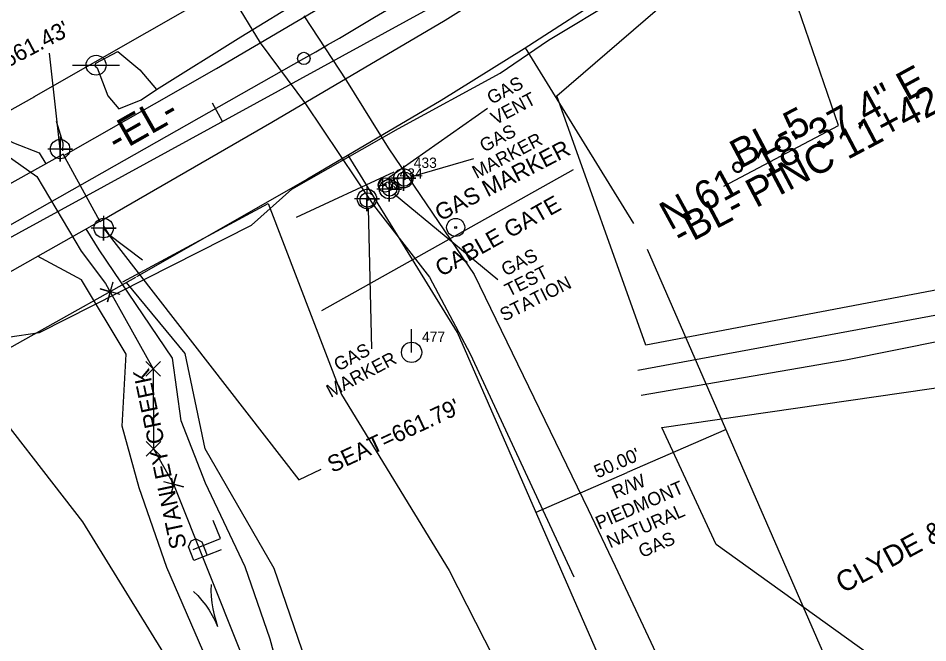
# Model space of a CAD drawing. Extents: x 1380524 to 1382335, y 594765 to 596944.
# Drawn here: x 1381675.7 to 1381895.1, y 595421 to 595571.8 of the extents above; entities that cross this region are included whole.
import ezdxf

# ---------------------------------------------------------------- set-up
doc = ezdxf.new("R2010")
doc.units = 0
for name, color, linetype in [('DTM Contours Minor Text', 7, 'Continuous'), ('Exist DTM Regular Point CELL', 7, 'Continuous'), ('Exist Horizontal Alignment', 7, 'Continuous'), ('Exist Horizontal Alignment Direction Label', 7, 'Continuous'), ('Exist Horizontal Alignment Station Label', 7, 'Continuous'), ('Exist Horizontal Baseline Alignment', 7, 'Continuous'), ('Exist Horizontal Baseline Alignment Direction Label', 7, 'Continuous'), ('Exist Horizontal Baseline Alignment Station Label', 7, 'Continuous'), ('Exist Horizontal Baseline Alignment Tick small', 7, 'Continuous'), ('Exist Hydro Jurisdictional Stream or Body of Water', 7, 'Continuous'), ('Exist Hydro Jurisdictional Stream or Body of Water Text', 7, 'Continuous'), ('Exist Other Culture Fence Line', 7, 'Continuous'), ('Exist Right of Way Line', 7, 'Continuous'), ('Exist Roads Concrete Median Barrier Cogo Comment', 7, 'Continuous'), ('Exist Roads EOP', 7, 'Continuous'), ('Exist Structure Major Bridge Seat Cogo Point CELL', 7, 'Continuous'), ('Exist Structure Major Bridge Seat Top Elevation', 7, 'Continuous'), ('Exist Structure Major Bridge WW', 7, 'Continuous'), ('Exist Utilities Gas UG Line', 7, 'Continuous'), ('Exist Utilities Gas UG Line Cogo Number', 7, 'Continuous'), ('Exist Utilities Gas UG Line Cogo Point CELL', 7, 'Continuous'), ('Exist Utilities Gas UG Line SUE', 7, 'Continuous'), ('Exist Utilities Other Located Object Leader', 7, 'Continuous'), ('Exist Utilities Power Tower CELL', 7, 'Continuous'), ('Exist Utilities Power Tower Text', 7, 'Continuous'), ('Exist Utilities Telephone UG Cable', 7, 'Continuous'), ('Exist Vegetation Tree CELL', 7, 'Continuous'), ('Prop Approach Slab Hatching', 7, 'Continuous'), ('Prop Drainage Ditch Boundaries', 7, 'Continuous'), ('Prop Drainage Structure Pipe Elbow CELL', 7, 'Continuous'), ('Prop Earthen Structure Cut Ditch Special Detail CELL', 7, 'Continuous'), ('Prop Earthen Structure Cut Ditch Special Detail Label', 7, 'Continuous'), ('Prop Earthen Structure Ditch Flow Line', 7, 'Continuous'), ('Prop Earthen Structure V Ditch Lateral Detail Label', 7, 'Continuous'), ('Prop Erosion Rip Rap Pad at Outlet CELL', 7, 'Continuous'), ('Prop Horizontal Alignment Tick Small', 7, 'Continuous'), ('Prop Plan Preparation Design Box Number Symbol CELL', 7, 'Continuous'), ('Scratch_Level_5', 7, 'Continuous'), ('Scratch_Level_6', 7, 'Continuous')]:
    doc.layers.add(name, color=color, linetype=linetype)

# ---------------------------------------------------------------- blocks, each defined once
blk = doc.blocks.new('EXIST UTILITIES OTHER LOCATED OBJECT')
at = {"layer": 'Prop Earthen Structure Cut Ditch Special Detail CELL'}
for radius in [0.0436, 0.0048]:
    blk.add_circle((0, 0), radius, dxfattribs=at)
blk = doc.blocks.new('EXIST HYDRO STREAM FLOW ARROW')
at = {"layer": 'DTM Contours Minor Text'}
blk.add_line((0, 0), (0, 0), dxfattribs=at)
for points in [[(-0.1, 0.04575), (-0.07325, 0.03375), (-0.04475, 0.0245), (-0.0165, 0.01575), (0.01175, 0.0095), (0.041, 0.00475), (0.07075, 0.0015), (0.1, 0)], [(-0.1, -0.04575), (-0.07325, -0.03375), (-0.04475, -0.0245), (-0.0165, -0.01575), (0.01175, -0.0095), (0.041, -0.00475), (0.07075, -0.0015), (0.1, 0)]]:
    blk.add_lwpolyline(points, dxfattribs=at)
blk = doc.blocks.new('EXIST UTILITIES POWER POLE')
at = {"layer": 'Exist Other Culture Fence Line'}
for q in [(0, 0.1125), (0, 0)]:
    blk.add_line((0, 0), q, dxfattribs=at)
blk.add_circle((0, 0), 0.049, dxfattribs=at)
blk = doc.blocks.new('EXIST UTILITIES TELEPHONE POLE')
at = {"layer": 'Exist Horizontal Alignment Station Label'}
for p, q in [((-0.1135, 0), (0.11325, 0)), ((0, 0), (0, 0))]:
    blk.add_line(p, q, dxfattribs=at)
blk.add_circle((0, 0), 0.04813, dxfattribs=at)
blk = doc.blocks.new('EXIST DTM REGULAR POINT')
at = {"layer": 'Exist DTM Regular Point CELL'}
blk.add_lwpolyline([(0, 0.06), (0, -0.06), (0, 0), (0.06, 0), (-0.06, 0)], dxfattribs=at)
blk.add_circle((0, 0), 0.0469, dxfattribs=at)

msp = doc.modelspace()

# ---------------------------------------------------------------- linework, layer by layer
at = {"layer": 'Exist Horizontal Alignment'}
msp.add_line((1381626.55, 595495.13), (1381744.58, 595562.07), dxfattribs=at)
msp.add_line((1381626.55, 595495.13), (1381744.58, 595562.07), dxfattribs=at)
msp.add_line((1381626.55, 595495.13), (1381744.58, 595562.07), dxfattribs=at)
msp.add_line((1381626.55, 595495.13), (1381744.58, 595562.07), dxfattribs=at)
msp.add_line((1381626.55, 595495.13), (1381744.58, 595562.07), dxfattribs=at)
msp.add_arc((1381362.24, 596236.19), 775, 299.56117, 307.3503, dxfattribs=at)
msp.add_arc((1381362.24, 596236.19), 775, 299.56117, 307.3503, dxfattribs=at)
msp.add_arc((1381362.24, 596236.19), 775, 299.56117, 307.3503, dxfattribs=at)
at = {"layer": 'Exist Horizontal Alignment Station Label'}
msp.add_circle((1381744.58, 595562.07), 1.5, dxfattribs=at)
at = {"layer": 'Exist Horizontal Baseline Alignment'}
msp.add_line((1381525.59, 595437.8), (1381849.7, 595615.17), dxfattribs=at)
at = {"layer": 'Exist Horizontal Baseline Alignment Station Label'}
for p, q in [((1381873.53, 595545.87), (1381849.7, 595615.17)), ((1381845.84, 595531.27), (1381873.53, 595545.87))]:
    msp.add_line(p, q, dxfattribs=at)
at = {"layer": 'Exist Horizontal Baseline Alignment Tick small'}
msp.add_line((1381724.92, 595546.88), (1381722.52, 595551.27), dxfattribs=at)
at = {"layer": 'Exist Hydro Jurisdictional Stream or Body of Water'}
for p, q in [((1381721.19, 595443.66), (1381721.19, 595443.66)), ((1381738.37, 595414.72), (1381736.48, 595421.87))]:
    msp.add_line(p, q, dxfattribs=at)
for points in [[(1381646.87, 595556.21), (1381674.51, 595541.69), (1381680.7, 595539.3), (1381682.35, 595536.63)], [(1381736.48, 595421.87), (1381730.41, 595439.34), (1381720.83, 595459.54), (1381715.01, 595474.58), (1381712.85, 595489.73), (1381695.18, 595515.91), (1381692.08, 595520.92)], [(1381721.27, 595416.77), (1381711.49, 595439.2), (1381704.86, 595458.45), (1381700.71, 595473.32), (1381701.7, 595490.68), (1381690.96, 595508.6), (1381680.33, 595514.31)], [(1381717.91, 595443.57), (1381724.48, 595446.19), (1381722.73, 595450.58)], [(1381724.59, 595443.45), (1381718.07, 595440.85), (1381716.75, 595444.16), (1381717.41, 595445.67), (1381718.49, 595446.1), (1381719.94, 595445.43), (1381721.26, 595442.12)]]:
    msp.add_lwpolyline(points, dxfattribs=at)
at = {"layer": 'Exist Other Culture Fence Line'}
for q in [(1381770.57, 595496.75), (1381770.57, 595491.13)]:
    msp.add_line((1381770.57, 595491.13), q, dxfattribs=at)
msp.add_circle((1381770.57, 595491.13), 2.45, dxfattribs=at)
at = {"layer": 'Exist Roads Concrete Median Barrier Cogo Comment'}
msp.add_line((1381742.83, 595523.74), (1381766.37, 595534.71), dxfattribs=at)
at = {"layer": 'Exist Roads EOP'}
for p, q in [((1381824.17, 595522.24), (1381798, 595564.6)), ((1381781.63, 595495.96), (1381755.23, 595538.7)), ((1381919.44, 595305.02), (1381827.47, 595515.95)), ((1381873.61, 595285.03), (1381781.63, 595495.96))]:
    msp.add_line(p, q, dxfattribs=at)
for points in [[(1381895.92, 595822.17), (1381902.47, 595793.76), (1381906.2, 595769.7), (1381907.97, 595742.61), (1381907.23, 595714.6), (1381902.73, 595686.65), (1381893.97, 595660.65), (1381884.45, 595642.32), (1381871.1, 595622.85), (1381855.36, 595606.07), (1381838.64, 595592.06), (1381819.68, 595578.62), (1381797.68, 595564.39), (1381777.69, 595551.91), (1381745.42, 595532.92), (1381704.18, 595509.33)], [(1381847.19, 595810.94), (1381853.34, 595784.3), (1381856.45, 595764.22), (1381857.93, 595741.64), (1381857.34, 595719.26), (1381854.03, 595698.69), (1381847.82, 595680.28), (1381841.48, 595668.07), (1381832.02, 595654.27), (1381820.95, 595642.47), (1381808.08, 595631.69), (1381791.64, 595620.03), (1381770.85, 595606.59), (1381751.76, 595594.66), (1381720.33, 595576.17), (1381679.35, 595552.72)], [(1381679.58, 595552.82), (1381632.97, 595526.73)], [(1381704, 595509.19), (1381657.4, 595483.1)]]:
    msp.add_lwpolyline(points, dxfattribs=at)
at = {"layer": 'Exist Structure Major Bridge Seat Top Elevation'}
msp.add_line((1381685.78, 595540.19), (1381683.22, 595563.35), dxfattribs=at)
at = {"layer": 'Exist Structure Major Bridge WW'}
for p, q in [((1381697.86, 595505.75), (1381697.86, 595505.75)), ((1381708.21, 595487.15), (1381708.21, 595487.15)), ((1381708.31, 595467.85), (1381708.31, 595467.85)), ((1381713.16, 595459.32), (1381713.16, 595459.32))]:
    msp.add_line(p, q, dxfattribs=at)
for points in [[(1381700.27, 595505.06), (1381695.46, 595506.43), (1381697.86, 595505.75), (1381697.18, 595503.34), (1381698.55, 595508.15)], [(1381709.98, 595485.4), (1381706.43, 595488.91), (1381708.21, 595487.15), (1381706.45, 595485.38), (1381709.97, 595488.93)], [(1381706.53, 595469.61), (1381710.08, 595466.1), (1381708.31, 595467.85), (1381710.07, 595469.63), (1381706.55, 595466.08)], [(1381710.75, 595459.98), (1381715.57, 595458.65), (1381713.16, 595459.32), (1381713.82, 595461.73), (1381712.5, 595456.91)]]:
    msp.add_lwpolyline(points, dxfattribs=at)
at = {"layer": 'Exist Utilities Gas UG Line'}
msp.add_lwpolyline([(1381819.69, 595439.52), (1382072.96, 594899.37)], dxfattribs=at)
at = {"layer": 'Exist Utilities Gas UG Line Cogo Point CELL'}
for points in [[(1381768.57, 595536.14), (1381768.57, 595530.14), (1381768.57, 595533.14), (1381771.57, 595533.14), (1381765.57, 595533.14)], [(1381765.15, 595533.53), (1381765.15, 595527.53), (1381765.15, 595530.53), (1381768.15, 595530.53), (1381762.15, 595530.53)], [(1381759.79, 595531.18), (1381759.79, 595525.18), (1381759.79, 595528.18), (1381762.79, 595528.18), (1381756.79, 595528.18)]]:
    msp.add_lwpolyline(points, dxfattribs=at)
for centre in [(1381768.57, 595533.14), (1381765.15, 595530.53), (1381759.79, 595528.18)]:
    msp.add_circle(centre, 2.34, dxfattribs=at)
at = {"layer": 'Exist Utilities Gas UG Line SUE'}
for p, q in [((1381723.79, 595582.73), (1381734.02, 595565.83)), ((1381744.6, 595572.32), (1381754.84, 595556.7)), ((1381734.02, 595565.83), (1381744.96, 595551.13)), ((1381754.84, 595556.7), (1381764.9, 595540.5)), ((1381744.96, 595551.13), (1381761.36, 595526.66)), ((1381764.9, 595540.5), (1381771.16, 595531.2)), ((1381771.16, 595531.2), (1381785.62, 595509.93)), ((1381761.36, 595526.66), (1381774.88, 595509.3)), ((1381774.88, 595509.3), (1381784.71, 595490.75)), ((1381785.62, 595509.93), (1381813.12, 595453.18)), ((1381784.71, 595490.75), (1381809.66, 595436.98)), ((1381813.12, 595453.18), (1381819.69, 595439.52))]:
    msp.add_line(p, q, dxfattribs=at)
at = {"layer": 'Exist Utilities Other Located Object Leader'}
for points in [[(1381765.09, 595533.32), (1381788.88, 595550.05)], [(1381770.61, 595533.58), (1381785.57, 595537.94)], [(1381766.46, 595529.33), (1381791.39, 595508.69)], [(1381760.08, 595525.97), (1381760.91, 595491.95)]]:
    msp.add_lwpolyline(points, dxfattribs=at)
at = {"layer": 'Exist Utilities Power Tower CELL'}
for p in [(1381846.4, 595472.53), (1381800.57, 595452.54)]:
    msp.add_line(p, (1381822.59, 595462.15), dxfattribs=at)
at = {"layer": 'Exist Utilities Power Tower Text'}
for p, q in [((1381697.86, 595505.75), (1381708.21, 595487.15)), ((1381708.21, 595487.15), (1381708.31, 595467.85)), ((1381708.31, 595467.85), (1381713.16, 595459.32)), ((1381713.16, 595459.32), (1381729.39, 595418.62))]:
    msp.add_line(p, q, dxfattribs=at)
at = {"layer": 'Exist Utilities Telephone UG Cable'}
for p, q in [((1381803.59, 595566.49), (1381829.59, 595582.19)), ((1381729.38, 595567.32), (1381749.29, 595579.5)), ((1381709.07, 595554.61), (1381729.38, 595567.32)), ((1381791.91, 595558.49), (1381803.59, 595566.49)), ((1381694.38, 595560.93), (1381699.7, 595563.71)), ((1381699.7, 595563.71), (1381705, 595559.32)), ((1381694.23, 595560.24), (1381694.38, 595560.93)), ((1381694.22, 595560.22), (1381694.74, 595559.79)), ((1381694.74, 595559.79), (1381697.26, 595553.01)), ((1381705, 595559.32), (1381709.07, 595554.61)), ((1381767.37, 595545.18), (1381791.91, 595558.49)), ((1381705.35, 595552.09), (1381709.07, 595554.61)), ((1381697.26, 595553.01), (1381699.93, 595549.91)), ((1381699.93, 595549.91), (1381705.35, 595552.09)), ((1381741.69, 595530.52), (1381767.37, 595545.18)), ((1381731.94, 595521.84), (1381741.69, 595530.52)), ((1381680.78, 595495.88), (1381731.94, 595521.84)), ((1381673.21, 595494.83), (1381680.78, 595495.88))]:
    msp.add_line(p, q, dxfattribs=at)
at = {"layer": 'Prop Drainage Ditch Boundaries'}
for points in [[(1381686.52, 595538.96), (1381642.72, 595514.47), (1381651.83, 595498.26)], [(1381651.83, 595498.26), (1381695.38, 595522.78), (1381686.52, 595538.96)]]:
    msp.add_lwpolyline(points, dxfattribs=at)
at = {"layer": 'Prop Drainage Structure Pipe Elbow CELL'}
for points in [[(1381991.91, 595521.81), (1381989.38, 595510.26), (1381981.68, 595508.51), (1381947.69, 595507.62), (1381920.27, 595504.37), (1381825.14, 595486.78)], [(1381825.94, 595480.83), (1381875.26, 595489.35), (1381922.43, 595498.8), (1381960.89, 595500.83), (1381987.45, 595500.26), (1382004.5, 595499.71), (1382013.34, 595497.39)]]:
    msp.add_lwpolyline(points, dxfattribs=at)
at = {"layer": 'Prop Earthen Structure Cut Ditch Special Detail Label'}
for points in [[(1381970.28, 595535.93), (1381960.54, 595518.19), (1381827.03, 595492.89), (1381805.59, 595553.01), (1381851.27, 595592.48), (1381878.01, 595618.84), (1381895.83, 595614.04), (1381941.37, 595569.31), (1381971.15, 595535.75)], [(1381700.88, 595508.12), (1381736, 595527.09), (1381753.67, 595480.99), (1381779.65, 595438.47), (1381803.04, 595392.5), (1381826.97, 595341.11)], [(1381810.86, 595331.84), (1381798.77, 595342.6), (1381770.6, 595350.31), (1381753.89, 595390.83), (1381737.44, 595438.95), (1381720.76, 595467.88), (1381715.91, 595490.83), (1381701.76, 595508)], [(1381909.46, 595397.71), (1381844.05, 595444.77), (1381830.9, 595473.02), (1381914.86, 595485.13), (1381966.96, 595492.75), (1381992.9, 595490.3), (1382011.42, 595478.91)], [(1381605.49, 595459.01), (1381664.85, 595484.17), (1381691.18, 595450.22), (1381713.09, 595414.76), (1381731.32, 595375.66), (1381749.27, 595334.34), (1381755.49, 595326.83), (1381786.26, 595322.65), (1381793.66, 595317.36)]]:
    msp.add_lwpolyline(points, dxfattribs=at)
at = {"layer": 'Prop Earthen Structure Ditch Flow Line'}
for points in [[(1381695.4, 595522.74), (1381736.81, 595546.71), (1381778.65, 595571.33), (1381805.29, 595588.06), (1381825.76, 595602.01), (1381844.65, 595617.61), (1381860.52, 595635.43), (1381873.02, 595654.26), (1381883.82, 595678.23), (1381890.26, 595702.1), (1381892.88, 595724.32), (1381892.54, 595747.98), (1381889.9, 595776.18), (1381882.89, 595811.47), (1381872.74, 595847.05), (1381870.77, 595854.96), (1381871.9, 595862.06), (1381875.4, 595867.69)], [(1381686.7, 595538.62), (1381723.5, 595559.64), (1381752.33, 595576.66), (1381785.4, 595597.24), (1381806.72, 595611.59), (1381824.38, 595625.23), (1381839.64, 595640.2), (1381852.72, 595657.45), (1381860.22, 595671.32), (1381868.91, 595695.27), (1381872.89, 595719.75), (1381873.33, 595746.52), (1381871.37, 595770.38), (1381866.55, 595797.62), (1381860.1, 595823.76)]]:
    msp.add_lwpolyline(points, dxfattribs=at)
at = {"layer": 'Prop Earthen Structure V Ditch Lateral Detail Label'}
msp.add_line((1381748.92, 595501.25), (1381809.58, 595535.28), dxfattribs=at)
at = {"layer": 'Prop Erosion Rip Rap Pad at Outlet CELL'}
for points in [[(1381684.84, 595546.94), (1381686.41, 595541.66), (1381686.32, 595539.77)], [(1381696.13, 595521.78), (1381697.42, 595519.67), (1381705.63, 595513.44)]]:
    msp.add_lwpolyline(points, dxfattribs=at)
at = {"layer": 'Scratch_Level_5'}
msp.add_lwpolyline([(1381649.07, 595551.08), (1381663.28, 595545.49), (1381680.13, 595533.61), (1381690.84, 595515.54), (1381696.74, 595507.76), (1381708.21, 595487.15)], dxfattribs=at)
at = {"layer": 'Scratch_Level_6'}
msp.add_lwpolyline([(1381696.28, 595521.11), (1381743.34, 595460.39), (1381748.78, 595462.92)], dxfattribs=at)

# ---------------------------------------------------------------- block references
at = {"layer": 'Exist Horizontal Alignment Station Label', "xscale": 50, "yscale": 50}
msp.add_blockref('EXIST UTILITIES TELEPHONE POLE', (1381694.46, 595560.43), dxfattribs=at)
at = {"layer": 'Exist Other Culture Fence Line', "xscale": 50, "yscale": 50}
msp.add_blockref('EXIST UTILITIES POWER POLE', (1381770.57, 595491.13), dxfattribs=at)
at = {"layer": 'Exist Structure Major Bridge Seat Cogo Point CELL', "xscale": 50, "yscale": 50}
for p in [(1381685.78, 595540.19), (1381696.28, 595521.11)]:
    msp.add_blockref('EXIST DTM REGULAR POINT', p, dxfattribs=at)
at = {"layer": 'Prop Earthen Structure Cut Ditch Special Detail CELL'}
for p, xscale, yscale in [((1381768.81, 595532.96), 40, 40), ((1381764.24, 595531.53), 40, 40), ((1381765.28, 595530.6), 40, 40), ((1381759.87, 595527.92), 40, 40), ((1381781.19, 595521.29), 50, 50)]:
    msp.add_blockref('EXIST UTILITIES OTHER LOCATED OBJECT', p, dxfattribs=dict(at, xscale=xscale, yscale=yscale))
at = {"layer": 'Prop Plan Preparation Design Box Number Symbol CELL', "xscale": 50, "yscale": 50, "rotation": -68.35521944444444}
msp.add_blockref('EXIST HYDRO STREAM FLOW ARROW', (1381721.93, 595429.63), dxfattribs=at)

# ---------------------------------------------------------------- texts
at = {"layer": 'Exist Horizontal Alignment Direction Label'}
msp.add_text('-EL-', height=7, rotation=29.5612, dxfattribs=at).set_placement((1381699.5, 595539.03))
at = {"layer": 'Exist Horizontal Baseline Alignment Direction Label'}
msp.add_text('N 61%%d 18\' 37.4" E', height=7, rotation=28.6896, dxfattribs=at).set_placement((1381832.94, 595520.43))
at = {"layer": 'Exist Horizontal Baseline Alignment Station Label'}
msp.add_text('BL-5', height=7, rotation=27.7977, dxfattribs=at).set_placement((1381849.79, 595535.35))
at = {"layer": 'Exist Hydro Jurisdictional Stream or Body of Water Text'}
msp.add_text('STANLEY CREEK', height=4, rotation=101.9079, dxfattribs=at).set_placement((1381716.34, 595444.16))
at = {"layer": 'Exist Right of Way Line'}
msp.add_text('CLYDE & CHONG MILLMAN', height=5, rotation=28.4195, dxfattribs=at).set_placement((1381874.6, 595432.85))
at = {"layer": 'Exist Structure Major Bridge Seat Top Elevation'}
msp.add_text("SEAT=661.43'", height=4, rotation=27.7976, dxfattribs=at).set_placement((1381657.96, 595551.77))
at = {"layer": 'Exist Utilities Gas UG Line Cogo Number'}
for s, p in [('433', (1381771.07, 595535.64)), ('434', (1381767.65, 595533.03)), ('435', (1381762.29, 595530.68))]:
    msp.add_text(s, height=2.5, dxfattribs=at).set_placement(p)
at = {"layer": 'Exist Utilities Power Tower CELL'}
for s, p in [("50.00'", (1381815.43, 595460.68)), ('PIEDMONT', (1381815.79, 595448.29)), ('R/W', (1381819.72, 595455.67)), ('NATURAL', (1381818.47, 595443.78)), ('GAS', (1381826.14, 595441.45))]:
    msp.add_text(s, height=3.2, rotation=23.5597, dxfattribs=at).set_placement(p)
at = {"layer": 'Exist Vegetation Tree CELL'}
msp.add_text('477', height=2.5, dxfattribs=at).set_placement((1381773.07, 595493.63))
msp.add_text('477', height=2.5, dxfattribs=at).set_placement((1381773.07, 595493.63))
at = {"layer": 'Prop Approach Slab Hatching'}
msp.add_text('CABLE GATE', height=4, rotation=29.2898, dxfattribs=at).set_placement((1381777.7, 595509.28))
at = {"layer": 'Prop Horizontal Alignment Tick Small'}
for s, height, rotation, p in [('GAS', 3.2, 27.7977, (1381789.82, 595550.87)), ('VENT', 3.2, 27.7977, (1381790.75, 595545.94)), ('GAS', 3.2, 27.7977, (1381788.06, 595539.32)), ('MARKER', 3.2, 27.7977, (1381786.25, 595532.94)), ('GAS MARKER', 4, 27.1976, (1381777.51, 595522.7)), ('GAS', 3.2, 26.6849, (1381793.21, 595509.43)), ('TEST', 3.2, 26.6849, (1381794.04, 595504.48)), ('STATION', 3.2, 26.6849, (1381792.87, 595498.51)), ('GAS', 3.2, 27.7977, (1381752.88, 595486.48)), ('MARKER', 3.2, 27.7977, (1381751.06, 595480.09))]:
    msp.add_text(s, height=height, rotation=rotation, dxfattribs=at).set_placement(p)
at = {"layer": 'Scratch_Level_6'}
for s, height, rotation, p in [('-BL- PINC 11+42.24 ', 7, 27.7977, (1381835.65, 595516.43)), ("SEAT=661.79'", 4, 25, (1381751.43, 595461.96))]:
    msp.add_text(s, height=height, rotation=rotation, dxfattribs=at).set_placement(p)

doc.saveas('drawing.dxf')
